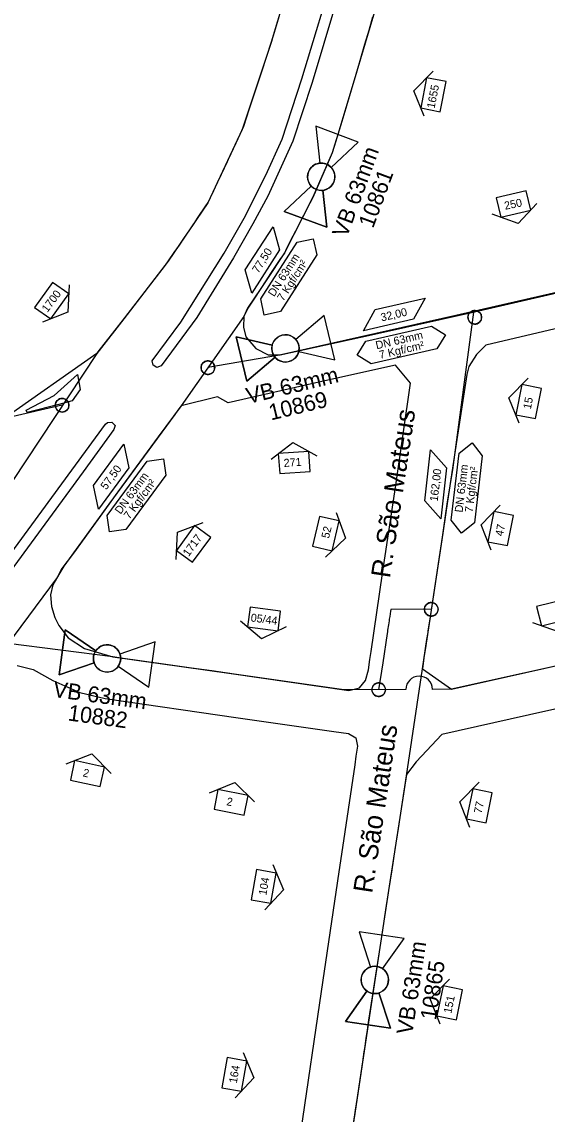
# Model space of a CAD drawing. Extents: x 656692 to 673945, y 7585994 to 7599066.
# Drawn here: x 669934.2 to 670131.1, y 7592057.7 to 7592467.1 of the extents above; entities that cross this region are included whole.
import ezdxf

# ---------------------------------------------------------------- set-up
doc = ezdxf.new("R2010")
doc.units = 0
for name, color, linetype in [('FORMATO', 7, 'Continuous'), ('LOGRADOURO', 7, 'Continuous'), ('LOGRADOURO_TEXTO', 7, 'Continuous'), ('NUM_REF', 7, 'Continuous'), ('SIMBOLO', 7, 'Continuous'), ('TEXTO', 7, 'Continuous'), ('TUBO_PEAD_GN_63', 7, 'Continuous'), ('VALVULA_PEAD_63', 7, 'Continuous')]:
    doc.layers.add(name, color=color, linetype=linetype)

# ---------------------------------------------------------------- blocks, each defined once
blk = doc.blocks.new('INTERLIGACAO_5')
at = {"layer": 'SIMBOLO'}
blk.add_circle((0, 0), 1.28, dxfattribs=at)
for start, end in [(0, 180), (180, 0)]:
    blk.add_arc((0, 0), 1.28, start, end, dxfattribs=at)
blk = doc.blocks.new('VALVULA_PEAD_DN_9')
at = {"layer": 'VALVULA_PEAD_63'}
for points in [[(-1.14, 0.57), (-4.25, 2.13), (-4.25, -2.13), (-1.14, -0.57)], [(-1.14, -0.57), (-4.25, -2.13), (-4.25, 2.13), (-1.14, 0.57)], [(1.14, -0.57), (4.25, -2.13), (4.25, 2.13), (1.14, 0.57)], [(1.14, -0.57), (4.25, -2.13), (4.25, 2.13), (1.14, 0.57)]]:
    blk.add_lwpolyline(points, dxfattribs=at)
blk.add_circle((0, 0), 1.28, dxfattribs=at)
for start, end in [(90, 270), (270, 90), (153.4349, 206.5651), (0, 26.5651), (333.4349, 0)]:
    blk.add_arc((0, 0), 1.28, start, end, dxfattribs=at)
blk = doc.blocks.new('NUM_REF_1')
at = {"layer": 'NUM_REF'}
blk.add_lwpolyline([(-4.3125, 0.9375), (0, 3.75), (4.3125, 0.9375)], dxfattribs=at)
blk.add_lwpolyline([(2.875, -1.875), (2.875, 1.875), (-2.875, 1.875), (-2.875, -1.875)], close=True, dxfattribs=at)

msp = doc.modelspace()

# ---------------------------------------------------------------- linework, layer by layer
at = {"layer": 'LOGRADOURO'}
for points in [[(670039.4, 7592498.41), (670028.44, 7592462), (670027.78, 7592459.76), (670016.85, 7592426.76), (670003.89, 7592399.28), (669989.06, 7592377.37), (669972.41, 7592355.72), (669962.26, 7592342.79), (669927.43, 7592318.3), (669923.67, 7592317.41), (669885.68, 7592308.83), (669847.29, 7592300.12), (669800.84, 7592289.76), (669793.04, 7592294.78), (669792.91, 7592295.32), (669792.53, 7592297.1), (669784.08, 7592340.06), (669780.99, 7592356.31), (669780.76, 7592357.42), (669773.22, 7592394.8), (669770.32, 7592412.26), (669770.63, 7592418.99), (669772.64, 7592423.29), (669781.16, 7592429.14)], [(670056.17, 7592488.32), (670042.98, 7592444.37), (670035.84, 7592422.36), (670026.36, 7592401.8), (670020.83, 7592391.39), (670013.6, 7592378.68), (669999.81, 7592356.25), (669986.42, 7592338.11), (669984.79, 7592337.58), (669983.45, 7592338.42), (669983.05, 7592340.1), (669993.8, 7592354.53), (670010.08, 7592380.43), (670017.53, 7592393.55), (670025.65, 7592409.57), (670031.85, 7592423.13), (670039.1, 7592445.67), (670052.29, 7592489.11)], [(670068.09, 7592476.88), (670054.2, 7592429.79), (670050.48, 7592417.99), (670043.25, 7592401.32), (670032.62, 7592380.46), (670018.86, 7592359.77), (670017.4, 7592356.7), (670017.29, 7592352.64), (670018.23, 7592349.07), (670021.87, 7592344.66), (670026.49, 7592342.32), (670031.02, 7592342.23), (670065.24, 7592349.84), (670103.9, 7592358.45), (670172.06, 7592374.16), (670263.59, 7592395.03), (670305.65, 7592404.77), (670313.71, 7592406.43), (670364.8, 7592418.15), (670443.12, 7592436.08), (670479.03, 7592444.59), (670484.13, 7592445.42), (670522.62, 7592454.17), (670524.99, 7592455.04)], [(670153.2, 7592356.49), (670108.12, 7592345.88), (670104.61, 7592342.37), (670101.79, 7592337.91), (670100.95, 7592334.94), (670097.24, 7592310.55), (670093.76, 7592287.44), (670091.96, 7592275.41), (670085.37, 7592231.7), (670084.88, 7592228.71), (670084.34, 7592224.67), (670095.23, 7592216.95), (670143.76, 7592227.87)], [(670074.22, 7592338.36), (670074.22, 7592338.36), (670046.6, 7592332.24), (670011.53, 7592324.35), (670007.55, 7592326.59), (669993.99, 7592323.19), (669992.65, 7592321.57), (669991.53, 7592319.98), (669966.78, 7592286.37), (669949.94, 7592263.13), (669948.11, 7592259.99), (669945.81, 7592256.04), (669944.95, 7592252.29), (669945.29, 7592247.94), (669946.6, 7592243.87), (669948.07, 7592240.82), (669951.51, 7592236.22), (669957.74, 7592232.18), (669968.26, 7592229.07), (670012.72, 7592222.82), (670056.84, 7592216.46), (670060.76, 7592217.52), (670063.01, 7592220.2), (670064.16, 7592224.29), (670064.67, 7592228.07), (670065.13, 7592231.1), (670069.42, 7592260.33), (670074.37, 7592293.47), (670079.92, 7592331.68), (670074.22, 7592338.36)], [(669936.16, 7592320.65), (669935.78, 7592321.6), (669946.27, 7592327.1), (669955.1, 7592334.9), (669956.07, 7592329.27), (669953.1, 7592325.11), (669948.11, 7592323.68), (669936.16, 7592320.65)], [(669825.71, 7592125.76), (669841.8, 7592147.85), (669866.73, 7592181.77), (669891.74, 7592215.81), (669917.34, 7592250.63), (669941.72, 7592283.69), (669965.55, 7592316.27), (669966.29, 7592316.98), (669967.94, 7592317.03), (669969.24, 7592315.84), (669968.73, 7592314.25), (669957.19, 7592298.43), (669931.2, 7592263.01), (669905.29, 7592227.68), (669879.59, 7592192.77), (669854.01, 7592157.86), (669828.71, 7592123.51), (669827.1, 7592123.01), (669825.75, 7592124.06), (669825.71, 7592125.76)], [(669932.44, 7592225.83), (669938.45, 7592224.32), (669945.78, 7592220.25), (669955.95, 7592215.73), (669965.4, 7592213.55), (670015.27, 7592206.3), (670051.19, 7592201.11), (670056.69, 7592200.36), (670059.44, 7592198.78), (670060.03, 7592195.6)], [(670163.5, 7592216.05), (670130.6, 7592208.69), (670091.68, 7592200), (670084.01, 7592191.87), (670082.07, 7592189.77), (670078.34, 7592185.04), (670072.15, 7592144.83), (670064.84, 7592097.22), (670059.01, 7592057.93), (670054.41, 7592028.54), (670054.19, 7592025.83), (670054.54, 7592022.85), (670056.73, 7592019.3), (670061.01, 7592016.93), (670066.54, 7592015.59), (670116.01, 7592025.7)], [(670060.03, 7592195.6), (670059.44, 7592191.9), (670058.97, 7592188.59), (670053.99, 7592155.13), (670053.01, 7592148.54), (670046.38, 7592103.68), (670038.75, 7592051.68)]]:
    msp.add_lwpolyline(points, dxfattribs=at)
at = {"layer": 'SIMBOLO'}
for points in [[(670030.8, 7592381.59), (670020.4, 7592365.42), (670017.97, 7592374.12), (670028.37, 7592390.29)], [(670081.05, 7592355.63), (670062.32, 7592351.31), (670066.65, 7592359.24), (670085.37, 7592363.56)], [(669974.37, 7592299.91), (669962.97, 7592284.44), (669961.09, 7592293.27), (669972.49, 7592308.75)], [(670093.45, 7592299.93), (670091.22, 7592280.84), (670085.21, 7592287.59), (670087.44, 7592306.68)]]:
    msp.add_lwpolyline(points, close=True, dxfattribs=at)
for points in [[(670025.07, 7592357.2), (670023.76, 7592363.25), (670037.42, 7592384.49), (670043.46, 7592385.8), (670044.78, 7592379.75), (670031.12, 7592358.51), (670025.07, 7592357.2)], [(670059.92, 7592342.16), (670063.2, 7592347.41), (670087.81, 7592353.09), (670093.05, 7592349.81), (670089.77, 7592344.56), (670065.17, 7592338.88), (670059.92, 7592342.16)], [(670099.03, 7592275.51), (670095.19, 7592280.36), (670098.12, 7592305.45), (670102.97, 7592309.28), (670106.81, 7592304.43), (670103.88, 7592279.35), (670099.03, 7592275.51)], [(669967.11, 7592275.94), (669966.18, 7592282.05), (669981.15, 7592302.39), (669987.27, 7592303.32), (669988.2, 7592297.2), (669973.23, 7592276.87), (669967.11, 7592275.94)]]:
    msp.add_lwpolyline(points, dxfattribs=at)
at = {"layer": 'TUBO_PEAD_GN_63'}
for points in [[(670065.7, 7592468.83), (670064.25, 7592463.88), (670062.68, 7592458.57), (670061.15, 7592453.41), (670059.72, 7592448.55), (670052.76, 7592425.27), (670051.33, 7592420.34), (670050.47, 7592417.97), (670048.66, 7592413.62), (670043.34, 7592401.31), (670042.16, 7592399.15), (670040.73, 7592396.37), (670039.23, 7592393.45), (670037.75, 7592390.54), (670035.81, 7592386.72), (670034.21, 7592383.59), (670033.06, 7592381.31), (670032.61, 7592380.41), (670031.19, 7592378.34), (670029.46, 7592375.72), (670027.45, 7592372.72), (670025.66, 7592370.01), (670023.74, 7592367.12), (670021.39, 7592363.6), (670018.84, 7592359.75), (670017.41, 7592356.71), (669993.91, 7592323.13), (669985.26, 7592311.59), (669970.24, 7592290.95), (669953.53, 7592267.96), (669949.21, 7592262.18), (669947.47, 7592258.79), (669906.87, 7592204.27)], [(670030.53, 7592468.97), (670028.44, 7592461.89), (670026.19, 7592454.88), (670023.64, 7592447.26), (670021.69, 7592441.27), (670019.25, 7592434.05), (670017.24, 7592427.92), (670014.43, 7592421.66), (670011.54, 7592415.55), (670011.11, 7592414.59), (670008.87, 7592409.85), (670007.44, 7592406.79), (670005.25, 7592402.16), (670003.95, 7592399.39), (670002.83, 7592397.75), (670000.21, 7592393.89), (669998.62, 7592391.54), (669996.79, 7592388.82), (669995.06, 7592386.27), (669993.13, 7592383.4), (669991.24, 7592380.62), (669989.36, 7592377.84), (669987.92, 7592375.91), (669972.72, 7592356.13), (669968.22, 7592350.43), (669963.59, 7592344.53), (669962.31, 7592342.88)], [(670302.94, 7592404.15), (670096.91, 7592357.08), (670030.83, 7592342.16), (670003.93, 7592337.49)], [(670103.51, 7592358.27), (670095.63, 7592299.25), (670093.68, 7592287.2), (670091.73, 7592273.99), (670090.89, 7592268.22), (670087.37, 7592244.96), (670087.21, 7592243.93), (670087.08, 7592243.03), (670086.92, 7592242.01), (670086.78, 7592241.03), (670086.67, 7592240.31), (670086.56, 7592239.61), (670086.45, 7592238.87), (670086.35, 7592238.19), (670086.26, 7592237.58), (670086.17, 7592236.94), (670086.05, 7592236.19), (670085.95, 7592235.55), (670084.32, 7592224.67), (670078.21, 7592184.47), (670075.25, 7592164.81), (670074.01, 7592156.88), (670072.85, 7592149.26), (670071.71, 7592141.55), (670070.53, 7592134.29), (670069.35, 7592126.67), (670068.11, 7592118.58), (670066.77, 7592109.75), (670065.5, 7592101.7), (670064.19, 7592092.94), (670063.93, 7592091.18), (670063.64, 7592089.13), (670063.31, 7592086.99), (670063.04, 7592085.14), (670062.73, 7592083.11), (670062.45, 7592081.06), (670062.16, 7592079.18), (670061.88, 7592077.33), (670060.91, 7592070.67), (670059.89, 7592063.98), (670059.2, 7592059.2), (670058.49, 7592054.9)], [(669962.33, 7592342.79), (669925.12, 7592286.69), (669883.98, 7592231.05), (669870.96, 7592213.21), (669858.29, 7592195.75), (669851.48, 7592186.47), (669844.53, 7592177.03), (669837.8, 7592167.85), (669784.21, 7592095.45), (669762.24, 7592065.17), (669754.79, 7592054.88)], [(669949.31, 7592323.38), (669907.57, 7592313.85)], [(670333.49, 7592270.26), (670211.36, 7592243.14), (670149.44, 7592228.99), (670095.23, 7592216.95), (670088.14, 7592216.91)], [(670087.67, 7592246.91), (670072.48, 7592246.83), (670072.38, 7592246.19), (670072.24, 7592245.25), (670072.09, 7592244.21), (670071.95, 7592243.25), (670071.84, 7592242.59), (670071.73, 7592241.84), (670071.61, 7592241.06), (670071.52, 7592240.43), (670071.42, 7592239.77), (670071.33, 7592239.15), (670071.23, 7592238.52), (670071.13, 7592237.85), (670069.49, 7592226.91), (670067.95, 7592216.8)], [(670078.14, 7592216.86), (670054.9, 7592216.73), (670031.23, 7592220.14), (670013.84, 7592222.65), (670005.39, 7592223.84), (669997.75, 7592224.91), (669989.04, 7592226.14), (669979.35, 7592227.49), (669971.29, 7592228.64), (669968.27, 7592229.06), (669929.09, 7592234.14)]]:
    msp.add_lwpolyline(points, dxfattribs=at)
msp.add_arc((670083.14, 7592216.89), 5, 0.3218, 180.3218, dxfattribs=at)

# ---------------------------------------------------------------- block references
at = {"layer": 'FORMATO'}
for p, xscale, yscale, rotation in [((670088.51, 7592439.78), 2, 2, 78.77481022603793), ((670118.48, 7592398.81), 2, 2.0000000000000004, -166.66750398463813), ((669945.37, 7592362.6), 2, 2, -125.40280284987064), ((670124.15, 7592324.76), 2, 2, 78.77481022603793), ((670036.34, 7592301.95), 2, 2, 4.041182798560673), ((670113.68, 7592277.16), 2, 2, 78.77481022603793), ((669998.6, 7592271.44), 2, 2, 53.858972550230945), ((670048.18, 7592275.28), 2, 2, -103.1753865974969), ((670025.02, 7592243.27), 1.9999999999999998, 1.9999999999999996, 172.54027264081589), ((670133.66, 7592245.73), 2, 2, -166.3811549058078), ((669958.81, 7592185.37), 1.9999999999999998, 1.9999999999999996, -12.36887862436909), ((670012.64, 7592174.61), 1.9999999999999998, 1.9999999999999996, -11.082178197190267), ((670105.73, 7592173.25), 2, 2, 78.3413599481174), ((670024.9, 7592143.06), 2, 2, -100.0900272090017), ((670094.61, 7592099.47), 2, 2, 78.3413599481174), ((670013.82, 7592072.61), 2, 2, -100.0900272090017)]:
    msp.add_blockref('NUM_REF_1', p, dxfattribs=dict(at, xscale=xscale, yscale=yscale, rotation=rotation))
at = {"layer": 'SIMBOLO'}
for p, xscale, yscale, rotation in [((670103.99, 7592356.35), 2, 2, -14.764722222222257), ((670003.93, 7592337.49), 2.0000000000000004, 1.9999999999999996, 73.0715289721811), ((669949.31, 7592323.38), 2, 2, 78.36118430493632), ((670087.67, 7592246.91), 2, 2, -14.764722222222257), ((670067.95, 7592216.8), 2, 2, -14.764722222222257)]:
    msp.add_blockref('INTERLIGACAO_5', p, dxfattribs=dict(at, xscale=xscale, yscale=yscale, rotation=rotation))
at = {"layer": 'VALVULA_PEAD_63'}
for p, xscale, yscale, rotation in [((670046.44, 7592409.04), 3.9999999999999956, 3.9999999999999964, 69.69495140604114), ((670033.02, 7592344.71), 3.9999999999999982, 3.9999999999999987, 13.57811851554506), ((669966.14, 7592228.51), 3.999999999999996, 3.9999999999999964, -7.670824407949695), ((670066.5, 7592108), 3.9999999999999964, 3.999999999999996, 81.31020411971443)]:
    msp.add_blockref('VALVULA_PEAD_DN_9', p, dxfattribs=dict(at, xscale=xscale, yscale=yscale, rotation=rotation))

# ---------------------------------------------------------------- texts
for s, height, rotation, p in [('1655', 3, 78.7748, (670088.9, 7592434.45)), ('VB 63mm', 6, 69.695, (670056, 7592385.89)), ('10861', 6, 69.695, (670065.85, 7592389.44)), ('250', 3, 11.8282, (670115.37, 7592396.63)), ('1700', 3, 53.0929, (669943.77, 7592357.97)), ('VB 63mm', 6, 13.5781, (670019.13, 7592323.87)), ('10869', 6, 13.5781, (670027.57, 7592317.68)), ('15', 3, 78.7748, (670124.99, 7592321.72)), ('271', 3, 4.0412, (670032.47, 7592300.26)), ('52', 3, 76.8246, (670049.34, 7592273.3)), ('47', 3, 78.7748, (670114.53, 7592274.12)), ('1717', 3, 53.859, (669996.71, 7592266.44)), ('05/44', 3, 352.5403, (670019.86, 7592242.39)), ('VB 63mm', 6, 352.3292, (669945.64, 7592214.11)), ('10882', 6, 352.3292, (669951.26, 7592205.28)), ('2', 3, 347.6311, (669956.89, 7592184.34)), ('2', 3, 348.9178, (670010.74, 7592173.54)), ('77', 3, 78.3414, (670106.55, 7592170.2)), ('104', 3, 79.91, (670025.84, 7592139.58)), ('VB 63mm', 6, 81.3102, (670080.52, 7592087.24)), ('10865', 6, 81.3102, (670089.45, 7592092.7)), ('151', 3, 78.3414, (670095.19, 7592095.28)), ('164', 3, 79.91, (670014.76, 7592069.13))]:
    msp.add_text(s, height=height, rotation=rotation).set_placement(p)
at = {"layer": 'LOGRADOURO_TEXTO'}
for p in [(670072.16, 7592258.39), (670065.5, 7592140.26)]:
    msp.add_text('R. São Mateus', height=7.2, rotation=81.3427, dxfattribs=at).set_placement(p)
at = {"layer": 'TEXTO'}
for s, rotation, p in [('77,50', 57.2597, (670022.81, 7592372.63)), ('DN 63mm', 57.2597, (670028.75, 7592363.84)), ('7 Kgf/cm²', 57.2597, (670032.19, 7592362.17)), ('32,00', 12.9963, (670069.08, 7592354.79)), ('DN 63mm', 12.9963, (670067.19, 7592344.35)), ('7 Kgf/cm²', 12.9963, (670068.49, 7592340.75)), ('DN 63mm', 83.3462, (670099.41, 7592283.09)), ('57,50', 53.6311, (669965.83, 7592291.48)), ('DN 63mm', 53.6311, (669971.2, 7592282.33)), ('162,00', 83.3462, (670090.07, 7592287.22)), ('7 Kgf/cm²', 83.3462, (670103.24, 7592283.11)), ('7 Kgf/cm²', 53.6311, (669974.53, 7592280.45))]:
    msp.add_text(s, height=3, rotation=rotation, dxfattribs=at).set_placement(p)

doc.saveas('drawing.dxf')
